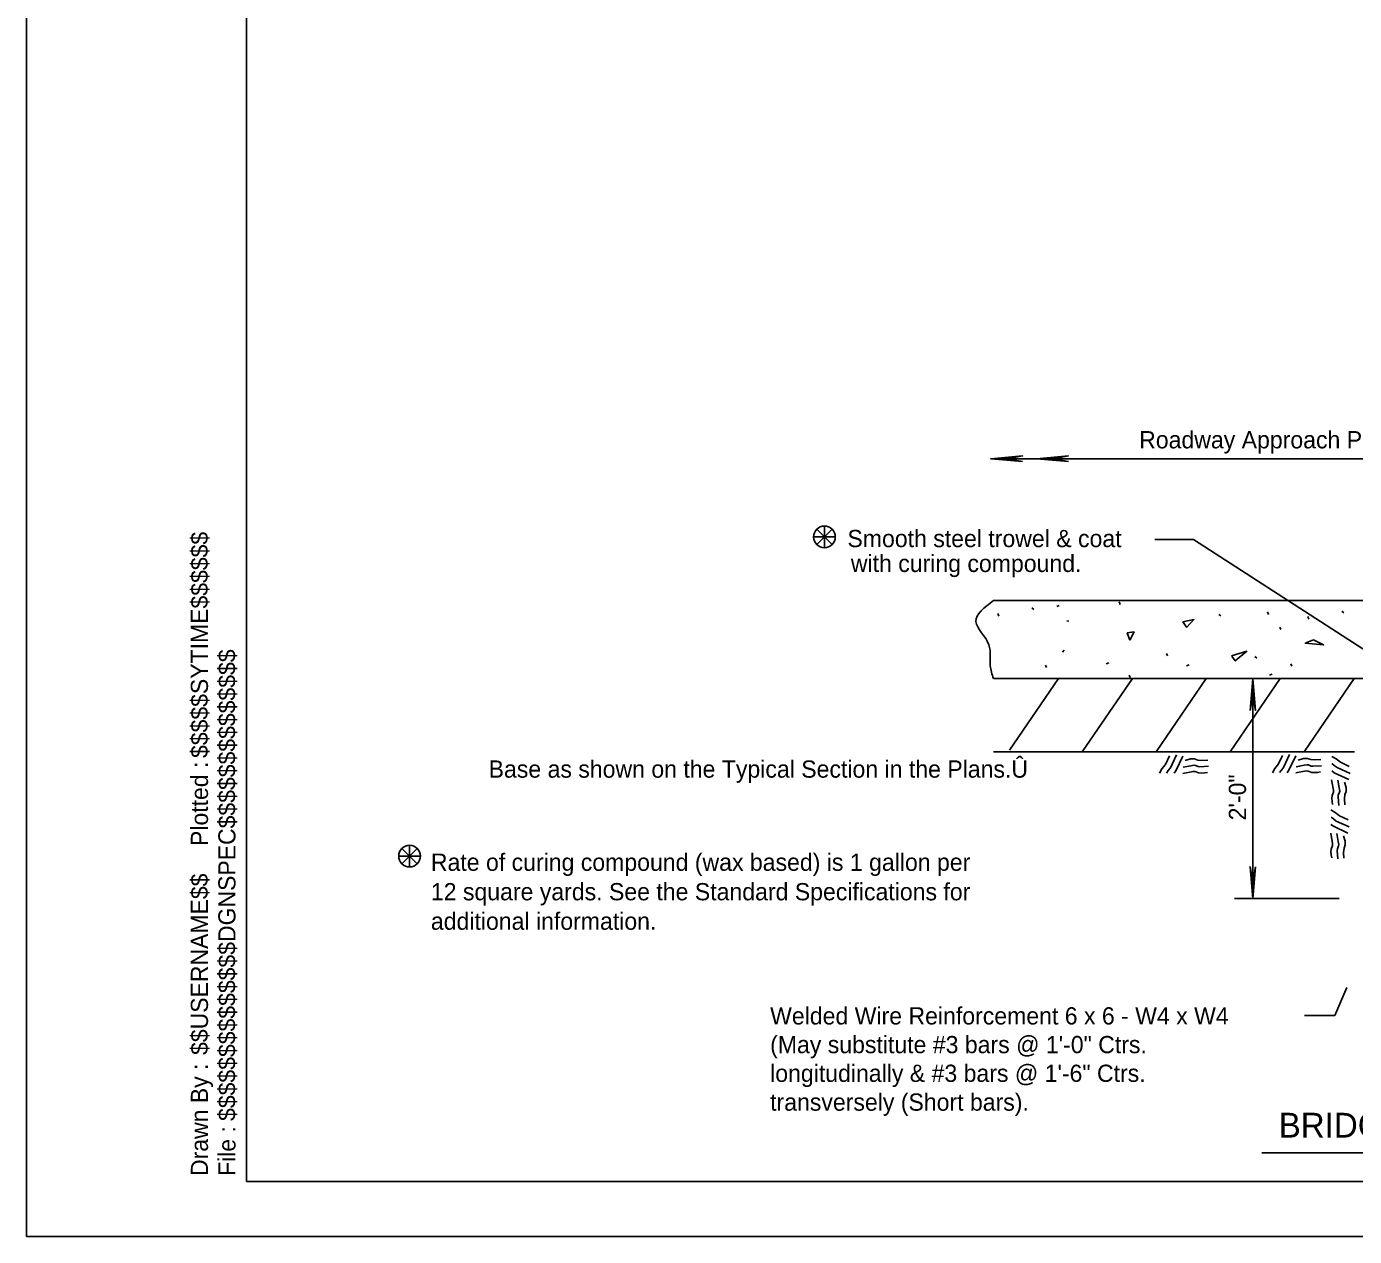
# Model space of a CAD drawing. Extents: x 1000 to 1036, y 1000 to 1022.7.
# Drawn here: x 1000 to 1012.07, y 1000 to 1011 of the extents above; entities that cross this region are included whole.
import ezdxf

# ---------------------------------------------------------------- set-up
doc = ezdxf.new("R2010")
doc.units = 0
for name, color, linetype in [('KS_Border Text_Z_N', 7, 'Continuous'), ('KS_Borders_Z_N', 7, 'Continuous'), ('KS_PlotShape_z_e', 7, 'Continuous'), ('rd_Area Patterns Normal_z_n', 7, 'Continuous'), ('rd_Detail Annotation_z_n', 7, 'Continuous'), ('rd_Details_z_n', 7, 'Continuous'), ('rd_Dimensions_z_n', 7, 'Continuous'), ('rd_Misc Label_z_n', 7, 'Continuous'), ('rd_Symbols_z_n', 7, 'Continuous')]:
    doc.layers.add(name, color=color, linetype=linetype)

msp = doc.modelspace()

# ---------------------------------------------------------------- linework, layer by layer
at = {"layer": 'KS_Borders_Z_N'}
for points in [[(999.998, 1021.998), (1035.998, 1021.998), (1035.998, 999.998), (999.998, 999.998)], [(1001.998, 1000.498), (1035.498, 1000.498), (1035.498, 1021.498), (1001.998, 1021.498)]]:
    msp.add_lwpolyline(points, close=True, dxfattribs=at)
at = {"layer": 'KS_PlotShape_z_e'}
msp.add_lwpolyline([(999.998, 999.998), (1035.998, 999.998), (1035.998, 1021.998), (999.998, 1021.998)], close=True, dxfattribs=at)
at = {"layer": 'rd_Area Patterns Normal_z_n'}
for points in [[(1010.3, 1004.209), (1010.323, 1004.249), (1010.354, 1004.289), (1010.391, 1004.368)], [(1010.455, 1004.376), (1010.401, 1004.259), (1010.381, 1004.233), (1010.365, 1004.211)], [(1010.512, 1004.365), (1010.449, 1004.232), (1010.433, 1004.209)], [(1010.535, 1004.325), (1010.583, 1004.339), (1010.618, 1004.34), (1010.648, 1004.329), (1010.686, 1004.326), (1010.74, 1004.329)], [(1011.328, 1004.214), (1011.351, 1004.253), (1011.382, 1004.294), (1011.419, 1004.372)], [(1011.484, 1004.38), (1011.429, 1004.263), (1011.41, 1004.237), (1011.393, 1004.216)], [(1011.54, 1004.369), (1011.478, 1004.237), (1011.461, 1004.213)], [(1011.563, 1004.329), (1011.611, 1004.343), (1011.646, 1004.344), (1011.676, 1004.334), (1011.714, 1004.33), (1011.768, 1004.333)], [(1011.867, 1004.363), (1011.907, 1004.34), (1011.947, 1004.309), (1012.026, 1004.272)], [(1010.737, 1004.217), (1010.711, 1004.212), (1010.68, 1004.211), (1010.657, 1004.213), (1010.625, 1004.224), (1010.606, 1004.226), (1010.514, 1004.208)], [(1010.516, 1004.265), (1010.587, 1004.278), (1010.615, 1004.282), (1010.627, 1004.281), (1010.653, 1004.27), (1010.668, 1004.269), (1010.746, 1004.274)], [(1011.765, 1004.222), (1011.739, 1004.216), (1011.708, 1004.215), (1011.685, 1004.217), (1011.654, 1004.228), (1011.634, 1004.23), (1011.542, 1004.212)], [(1011.544, 1004.269), (1011.615, 1004.282), (1011.644, 1004.287), (1011.655, 1004.285), (1011.681, 1004.274), (1011.696, 1004.273), (1011.774, 1004.278)], [(1012.022, 1004.151), (1011.89, 1004.213), (1011.867, 1004.23)], [(1012.034, 1004.207), (1011.917, 1004.262), (1011.89, 1004.281), (1011.869, 1004.298)], [(1011.875, 1003.926), (1011.87, 1003.952), (1011.869, 1003.983), (1011.871, 1004.006), (1011.882, 1004.037), (1011.884, 1004.056), (1011.866, 1004.149)], [(1011.923, 1004.147), (1011.936, 1004.076), (1011.94, 1004.047), (1011.939, 1004.036), (1011.927, 1004.009), (1011.927, 1003.995), (1011.932, 1003.916)], [(1011.983, 1004.128), (1011.997, 1004.08), (1011.998, 1004.044), (1011.987, 1004.015), (1011.984, 1003.977), (1011.987, 1003.923)], [(1011.859, 1003.876), (1011.898, 1003.853), (1011.939, 1003.822), (1012.017, 1003.785)], [(1012.014, 1003.665), (1011.882, 1003.727), (1011.858, 1003.744)], [(1012.025, 1003.721), (1011.908, 1003.775), (1011.882, 1003.795), (1011.861, 1003.811)], [(1011.867, 1003.439), (1011.862, 1003.466), (1011.86, 1003.496), (1011.862, 1003.519), (1011.873, 1003.551), (1011.875, 1003.57), (1011.858, 1003.663)], [(1011.914, 1003.66), (1011.927, 1003.589), (1011.932, 1003.561), (1011.93, 1003.549), (1011.919, 1003.523), (1011.918, 1003.508), (1011.923, 1003.43)], [(1011.974, 1003.641), (1011.988, 1003.593), (1011.989, 1003.558), (1011.979, 1003.528), (1011.975, 1003.49), (1011.978, 1003.436)]]:
    msp.add_lwpolyline(points, dxfattribs=at)
at = {"layer": 'rd_Detail Annotation_z_n'}
for p, q in [((1010.611, 1006.333), (1010.259, 1006.333)), ((1012.569, 1005.07), (1010.611, 1006.333)), ((1012.005, 1002.26), (1011.894, 1002.006)), ((1011.894, 1002.006), (1011.621, 1002.006)), ((1011.23, 1000.758), (1017.164, 1000.758))]:
    msp.add_line(p, q, dxfattribs=at)
at = {"layer": 'rd_Details_z_n'}
for p, q in [((1008.791, 1005.779), (1013.908, 1005.779)), ((1009.14, 1005.712), (1009.158, 1005.698)), ((1009.366, 1005.725), (1009.389, 1005.734)), ((1009.943, 1005.744), (1009.934, 1005.767)), ((1011.284, 1005.677), (1011.293, 1005.654)), ((1011.959, 1005.683), (1011.977, 1005.669)), ((1008.831, 1005.661), (1008.84, 1005.638)), ((1009.457, 1005.595), (1009.475, 1005.591)), ((1010.841, 1005.653), (1010.859, 1005.639)), ((1011.651, 1005.633), (1011.659, 1005.61)), ((1011.396, 1005.538), (1011.405, 1005.515)), ((1009.419, 1005.311), (1009.433, 1005.329)), ((1009.263, 1005.193), (1009.272, 1005.17)), ((1009.84, 1005.212), (1009.817, 1005.203)), ((1010.375, 1005.276), (1010.366, 1005.299)), ((1010.547, 1005.186), (1010.57, 1005.195)), ((1011.185, 1005.256), (1011.167, 1005.27)), ((1011.504, 1005.182), (1011.495, 1005.205)), ((1013.991, 1005.07), (1008.791, 1005.07)), ((1008.936, 1004.42), (1009.381, 1005.07)), ((1009.598, 1004.403), (1010.054, 1005.07)), ((1010.033, 1005.079), (1010.024, 1005.102)), ((1010.271, 1004.403), (1010.726, 1005.07)), ((1010.944, 1004.403), (1011.399, 1005.07)), ((1011.302, 1005.1), (1011.325, 1005.109)), ((1011.617, 1004.403), (1012.072, 1005.07)), ((1012.075, 1004.403), (1008.791, 1004.403))]:
    msp.add_line(p, q, dxfattribs=at)
for points in [[(1010.548, 1005.534), (1010.514, 1005.585), (1010.614, 1005.607), (1010.549, 1005.536)], [(1010.03, 1005.419), (1010.007, 1005.485), (1010.069, 1005.494), (1010.03, 1005.419)], [(1011.7, 1005.421), (1011.793, 1005.376), (1011.627, 1005.391), (1011.7, 1005.421)], [(1010.957, 1005.277), (1011.095, 1005.319), (1010.99, 1005.23), (1010.959, 1005.275)]]:
    msp.add_lwpolyline(points, dxfattribs=at)
msp.add_spline([(1008.791, 1005.779), (1008.632, 1005.589), (1008.75, 1005.376), (1008.762, 1005.187), (1008.791, 1005.07)], degree=3, dxfattribs=at)
at = {"layer": 'rd_Dimensions_z_n'}
for p, q in [((1008.766, 1007.069), (1013.95, 1007.069)), ((1011.149, 1003.07), (1011.149, 1005.07)), ((1010.982, 1003.07), (1011.936, 1003.07))]:
    msp.add_line(p, q, dxfattribs=at)
at = {"layer": 'rd_Misc Label_z_n'}
for points in [[(1009.056, 1007.044), (1008.766, 1007.069), (1009.056, 1007.095), (1008.916, 1007.069), (1009.056, 1007.044)], [(1009.472, 1007.044), (1009.182, 1007.069), (1009.472, 1007.095), (1009.332, 1007.069), (1009.472, 1007.044)], [(1011.124, 1004.781), (1011.149, 1005.07), (1011.174, 1004.781), (1011.149, 1004.92), (1011.124, 1004.781)], [(1011.174, 1003.359), (1011.149, 1003.07), (1011.124, 1003.359), (1011.149, 1003.22), (1011.174, 1003.359)]]:
    msp.add_lwpolyline(points, dxfattribs=at)
at = {"layer": 'rd_Symbols_z_n'}
for p, q in [((1007.184, 1006.289), (1007.323, 1006.428)), ((1007.323, 1006.289), (1007.184, 1006.428)), ((1007.254, 1006.457), (1007.254, 1006.26)), ((1007.156, 1006.358), (1007.352, 1006.358)), ((1003.412, 1003.387), (1003.551, 1003.526)), ((1003.551, 1003.387), (1003.412, 1003.526)), ((1003.481, 1003.555), (1003.481, 1003.358)), ((1003.383, 1003.456), (1003.58, 1003.456))]:
    msp.add_line(p, q, dxfattribs=at)
for centre in [(1007.254, 1006.358), (1003.481, 1003.456)]:
    msp.add_circle(centre, 0.0982, dxfattribs=at)

# ---------------------------------------------------------------- texts
at = {"layer": 'KS_Border Text_Z_N'}
for s, height, p in [('$$$$$SYTIME$$$$$$', 0.15625, (1001.648, 1004.348)), ('$$$$$$$$$$$$$$DGNSPEC$$$$$$$$$$$$$$', 0.15625, (1001.898, 1001.048)), ('Plotted :', 0.1562, (1001.648, 1003.548)), ('$$USERNAME$$', 0.15625, (1001.648, 1001.648)), ('Drawn By :', 0.1562, (1001.648, 1000.548)), ('File :', 0.1562, (1001.898, 1000.548))]:
    msp.add_text(s, height=height, rotation=90, dxfattribs=at).set_placement(p)
at = {"layer": 'rd_Detail Annotation_z_n'}
for s, height, p in [('Smooth steel trowel & coat', 0.15675, (1007.463, 1006.265)), ('with curing compound.', 0.15675, (1007.494, 1006.039)), ('Base as shown on the Typical Section in the Plans.Û', 0.15675, (1004.2, 1004.169)), ('Rate of curing compound (wax based) is 1 gallon per', 0.15675, (1003.675, 1003.322)), ('12 square yards. See the Standard Specifications for ', 0.15675, (1003.675, 1003.054)), ('additional information.', 0.15675, (1003.675, 1002.786)), ('Welded Wire Reinforcement 6 x 6 - W4 x W4', 0.15675, (1006.76, 1001.925)), ('(May substitute #3 bars @ 1\'-0" Ctrs.', 0.15675, (1006.76, 1001.664)), ('longitudinally & #3 bars @ 1\'-6" Ctrs.', 0.15675, (1006.76, 1001.403)), ('transversely (Short bars).', 0.15675, (1006.76, 1001.141)), ('BRIDGE APPROACH SLAB FOOTING', 0.225, (1011.385, 1000.897))]:
    msp.add_text(s, height=height, dxfattribs=at).set_placement(p)
at = {"layer": 'rd_Dimensions_z_n'}
msp.add_text('Roadway Approach Pavement', height=0.15675, dxfattribs=at).set_placement((1010.116, 1007.163))
msp.add_text('2\'-0"', height=0.1567, rotation=90, dxfattribs=at).set_placement((1011.088, 1003.781))

doc.saveas('drawing.dxf')
